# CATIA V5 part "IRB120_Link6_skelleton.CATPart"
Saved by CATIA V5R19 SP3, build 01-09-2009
Part number: IRB120_Link6_skelleton
Bounding box of the stored display mesh (mm): x 0 to 72, y 0 to 0, z 0 to 0
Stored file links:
  Z:\Projects\ABB_Robotics\ABB LIB\V5\V5PARTS\ABB\120\IRB120_Link6_skelleton.CATPart
  Z:\Projects\ABB_Robotics\ABB IRB2600\In data\V5_Files\IRB2600-12-165_4.CATProduct
  Z:\Projects\ABB_Robotics\ABB IRB2600\In data\V5_Files\IRB2600-12-165_Link5_skelleton.CATPart
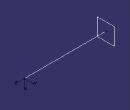
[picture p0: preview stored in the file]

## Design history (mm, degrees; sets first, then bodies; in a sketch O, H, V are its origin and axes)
Body1 (main body)
  Line1: type PtPt, FirstPoint {point type Coord, X 0, Y 0, Z 0}, SecondPoint {point type Coord, X 72, Y 0, Z 0, RefPoint {point type Coord, X 0, Y 0, Z 0}}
